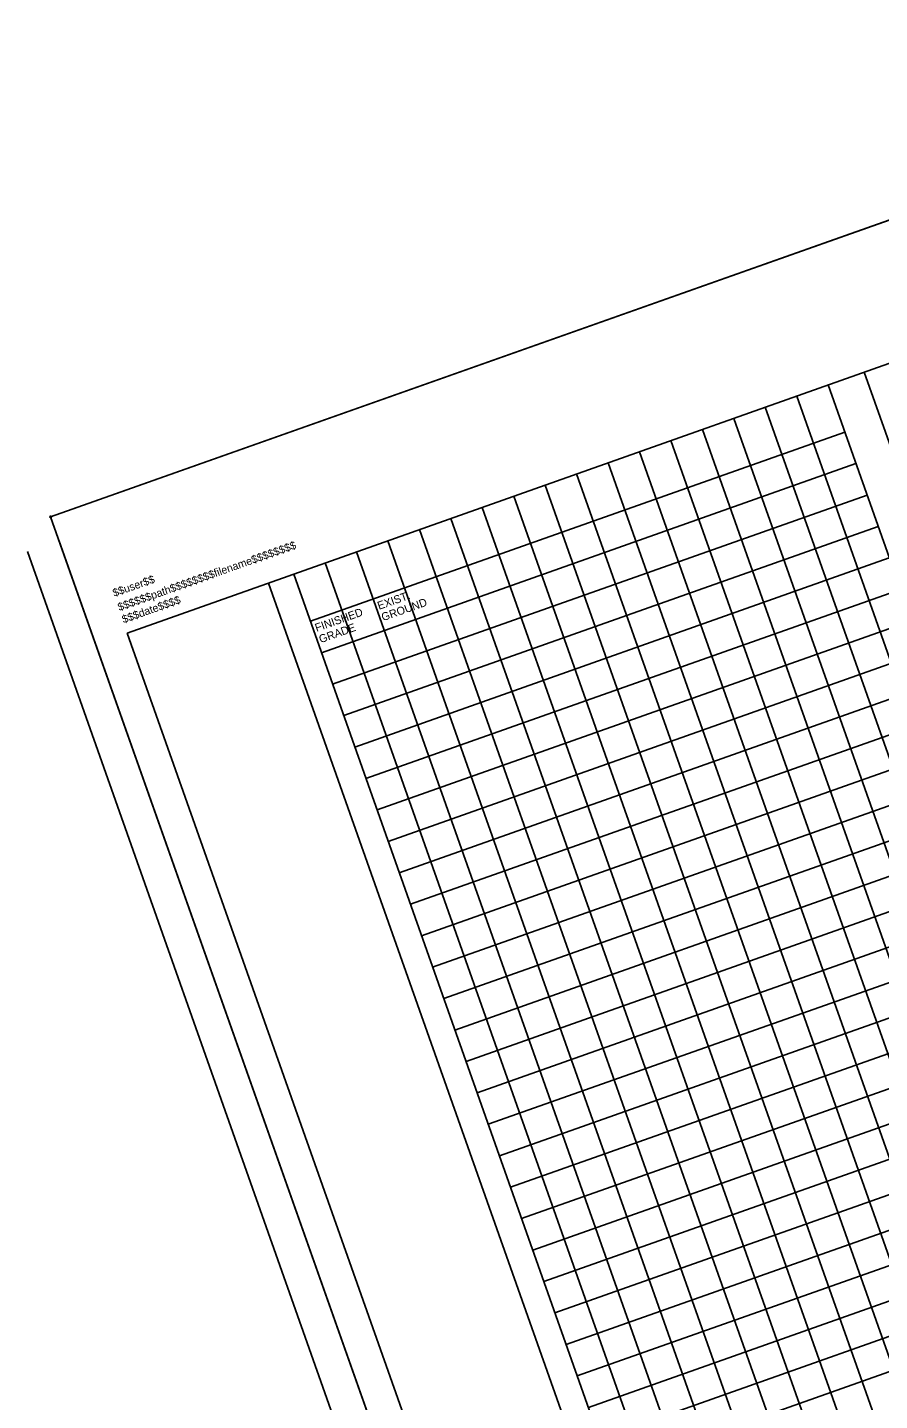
# Model space of a CAD drawing. Extents: x 2002686 to 2004357, y 1138437 to 1140501.
# Drawn here: x 2002686 to 2003325, y 1139472 to 1140501 of the extents above; entities that cross this region are included whole.
import ezdxf

# ---------------------------------------------------------------- set-up
doc = ezdxf.new("R2010")
doc.units = 0
for name, color, linetype in [('RD_SHT_Bndy', 7, 'Continuous'), ('RD_SHT_ID', 7, 'Continuous'), ('RD_SHT_IplotShp', 7, 'Continuous'), ('RD_SHT_MjGrid', 7, 'Continuous'), ('RD_SHT_MnGrid', 7, 'Continuous'), ('RD_SHT_Snap', 7, 'Continuous'), ('RD_SHT_TX', 7, 'Continuous')]:
    doc.layers.add(name, color=color, linetype=linetype)

msp = doc.modelspace()

# ---------------------------------------------------------------- linework, layer by layer
at = {"layer": 'RD_SHT_Bndy'}
for p, q in [((2003750.6, 1140397.3), (2002760.7, 1140047.1)), ((2003296.6, 1138457.4), (2002709.6, 1140116.7)), ((2003273, 1138449.1), (2002686, 1140108.3)), ((2003096.4, 1139435.4), (2002866.7, 1140084.6)), ((2002760.7, 1140047.1), (2003319.3, 1138468))]:
    msp.add_line(p, q, dxfattribs=at)
at = {"layer": 'RD_SHT_IplotShp'}
msp.add_lwpolyline([(2003740.4, 1140501.1), (2004340.7, 1138804.1), (2003303.7, 1138437.3), (2002703.4, 1140134.2)], close=True, dxfattribs=at)
msp.add_circle((2002703.4, 1140134.2), 0.607, dxfattribs=at)
msp.add_circle((2002703.4, 1140134.2), 0.607, dxfattribs=at)
msp.add_circle((2002703.4, 1140134.2), 0.607, dxfattribs=at)
msp.add_circle((2002703.4, 1140134.2), 0.607, dxfattribs=at)
at = {"layer": 'RD_SHT_MjGrid'}
for p, q in [((2003313.4, 1140242.6), (2003872, 1138663.5)), ((2003286.3, 1140233.1), (2003844.9, 1138654)), ((2003298.8, 1140197.7), (2002898.1, 1140056)), ((2003315.5, 1140150.6), (2002914.8, 1140008.8)), ((2002885.6, 1140091.3), (2003444.2, 1138512.2)), ((2003357.1, 1140032.7), (2002956.5, 1139891)), ((2003398.8, 1139914.9), (2002998.2, 1139773.1)), ((2003440.5, 1139797), (2003039.9, 1139655.3)), ((2003482.2, 1139679.2), (2003081.5, 1139537.5)), ((2003523.9, 1139561.4), (2003123.2, 1139419.6))]:
    msp.add_line(p, q, dxfattribs=at)
at = {"layer": 'RD_SHT_MnGrid'}
for p, q in [((2003262.7, 1140224.7), (2003758.8, 1138822.4)), ((2003239.1, 1140216.4), (2003797.8, 1138637.3)), ((2003215.6, 1140208), (2003774.2, 1138628.9)), ((2003192, 1140199.7), (2003750.6, 1138620.6)), ((2003144.9, 1140183), (2003703.5, 1138603.9)), ((2003168.4, 1140191.4), (2003727.1, 1138612.3)), ((2003307.1, 1140174.1), (2002906.4, 1140032.4)), ((2003121.3, 1140174.7), (2003679.9, 1138595.6)), ((2003097.7, 1140166.4), (2003656.4, 1138587.3)), ((2003074.2, 1140158), (2003632.8, 1138578.9)), ((2003027, 1140141.3), (2003585.6, 1138562.2)), ((2003050.6, 1140149.7), (2003609.2, 1138570.6)), ((2003003.4, 1140133), (2003562.1, 1138553.9)), ((2003323.8, 1140127), (2002923.1, 1139985.3)), ((2002979.9, 1140124.7), (2003538.5, 1138545.6)), ((2002956.3, 1140116.3), (2003514.9, 1138537.2)), ((2003332.1, 1140103.4), (2002931.5, 1139961.7)), ((2002932.7, 1140108), (2003491.4, 1138528.9)), ((2002909.2, 1140099.7), (2003467.8, 1138520.6)), ((2003340.5, 1140079.9), (2002939.8, 1139938.1)), ((2003348.8, 1140056.3), (2002948.1, 1139914.6)), ((2003365.5, 1140009.2), (2002964.8, 1139867.4)), ((2003373.8, 1139985.6), (2002973.1, 1139843.8)), ((2003382.2, 1139962), (2002981.5, 1139820.3)), ((2003390.5, 1139938.4), (2002989.8, 1139796.7)), ((2003407.2, 1139891.3), (2003006.5, 1139749.6)), ((2003415.5, 1139867.7), (2003014.8, 1139726)), ((2003423.8, 1139844.2), (2003023.2, 1139702.4)), ((2003432.2, 1139820.6), (2003031.5, 1139678.9)), ((2003448.9, 1139773.5), (2003048.2, 1139631.7)), ((2003457.2, 1139749.9), (2003056.5, 1139608.2)), ((2003465.5, 1139726.3), (2003064.9, 1139584.6)), ((2003473.9, 1139702.8), (2003073.2, 1139561)), ((2003490.5, 1139655.6), (2003089.9, 1139513.9)), ((2003498.9, 1139632.1), (2003098.2, 1139490.3)), ((2003507.2, 1139608.5), (2003106.6, 1139466.7)), ((2003515.6, 1139584.9), (2003114.9, 1139443.2))]:
    msp.add_line(p, q, dxfattribs=at)
at = {"layer": 'RD_SHT_Snap'}
msp.add_line((2002703.4, 1140134.2), (2003740.4, 1140501.1), dxfattribs=at)

# ---------------------------------------------------------------- texts
at = {"layer": 'RD_SHT_ID'}
for s, p in [('$$$$$$path$$$$$$$$filename$$$$$$$$', (2002754.9, 1140063.6)), ('$$user$$', (2002751.1, 1140074.2)), ('$$$date$$$$', (2002758.1, 1140054.4))]:
    msp.add_text(s, height=5.88, rotation=19.482, dxfattribs=at).set_placement(p)
at = {"layer": 'RD_SHT_TX'}
for s, p in [('EXIST.', (2002949.6, 1140064.5)), ('GROUND', (2002952.6, 1140056)), ('FINISHED', (2002902.8, 1140048)), ('GRADE', (2002905.8, 1140039.5))]:
    msp.add_text(s, height=6, rotation=19.482, dxfattribs=at).set_placement(p)

doc.saveas('drawing.dxf')
